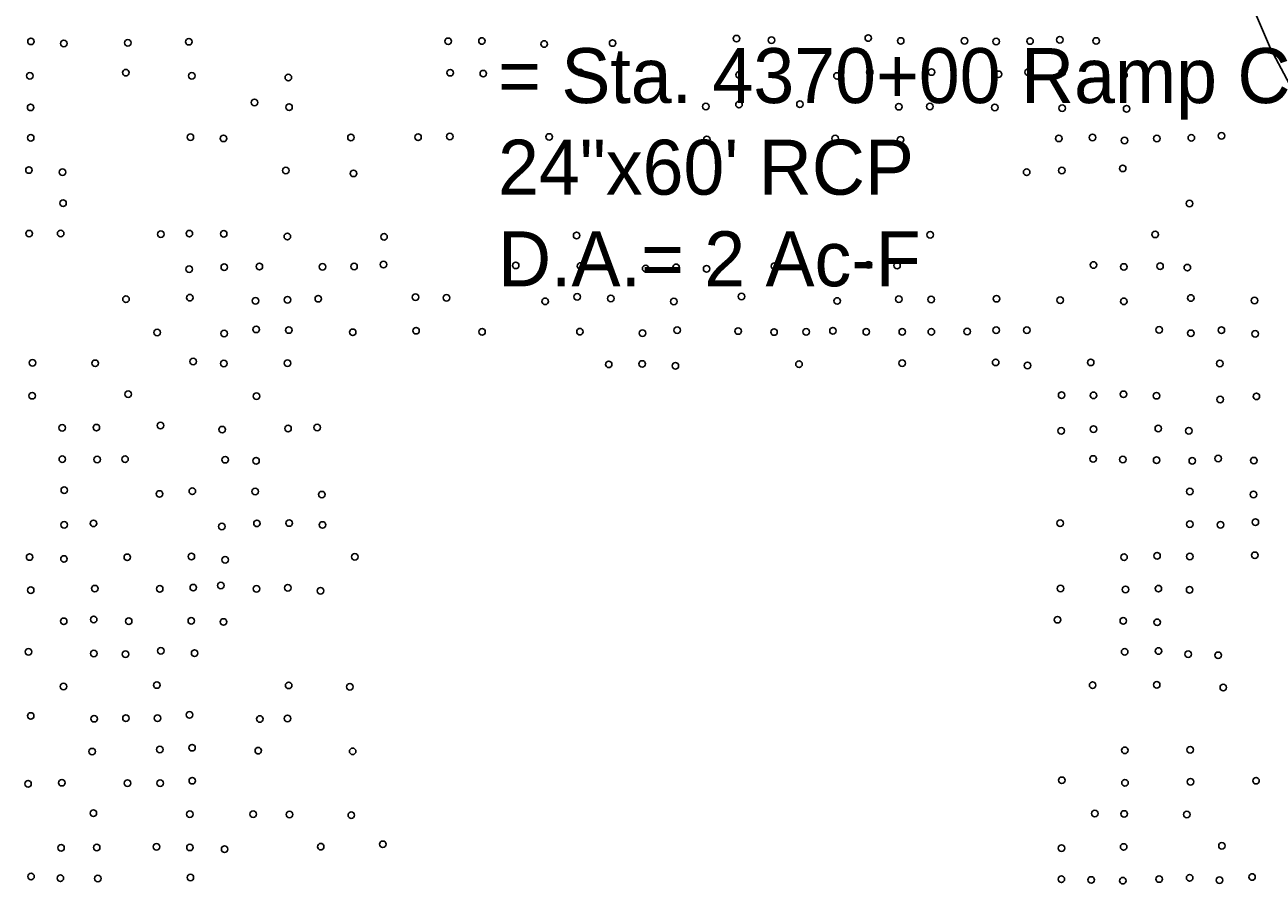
# Model space of a CAD drawing. Extents: x 20503438 to 20508873, y 7964251 to 7984667.
# Drawn here: x 20506056 to 20506434.7, y 7969482.5 to 7969745.2 of the extents above; entities that cross this region are included whole.
import ezdxf

# ---------------------------------------------------------------- set-up
doc = ezdxf.new("R2010")
doc.units = 0
for name, color, linetype in [('SurBreakLine', 7, 'Continuous'), ('SurSurveyPoints', 7, 'Continuous'), ('SurTxtDrainage', 7, 'Continuous')]:
    doc.layers.add(name, color=color, linetype=linetype)

msp = doc.modelspace()

# ---------------------------------------------------------------- linework, layer by layer
at = {"layer": 'SurBreakLine'}
msp.add_lwpolyline([(20506245.46, 7970059.26), (20506289.42, 7969989.86), (20506322.08, 7969939.84), (20506362.1, 7969878.45), (20506391.2, 7969829.89), (20506418.64, 7969776.17), (20506425.78, 7969763.92), (20506436.91, 7969737.91), (20506455.83, 7969702.3), (20506472.72, 7969660.29), (20506490.33, 7969606.63), (20506502.81, 7969561.31), (20506518.36, 7969500.09), (20506526.15, 7969455.03)], dxfattribs=at)
at = {"layer": 'SurSurveyPoints'}
for centre in [(20506057.92, 7969740.08), (20506067.96, 7969739.46), (20506087.52, 7969739.64), (20506106.22, 7969739.98), (20506185.5, 7969740.11), (20506195.81, 7969740.2), (20506214.85, 7969739.28), (20506235.76, 7969739.57), (20506273.66, 7969740.92), (20506284.32, 7969740.47), (20506313.93, 7969741.11), (20506323.84, 7969740.21), (20506343.38, 7969740.24), (20506353.02, 7969740.02), (20506363.38, 7969740.19), (20506372.48, 7969740.58), (20506383.6, 7969740.21), (20506225.82, 7969730.6), (20506314.37, 7969730.68), (20506333.23, 7969730.71), (20506362.81, 7969730.66), (20506373.21, 7969730.59), (20506057.59, 7969729.56), (20506086.93, 7969730.52), (20506107.1, 7969729.54), (20506136.61, 7969729.01), (20506186.12, 7969730.51), (20506196.22, 7969730.22), (20506274.42, 7969729.82), (20506304.37, 7969729.51), (20506353.75, 7969730.02), (20506392.12, 7969729.77), (20506057.82, 7969719.91), (20506126.25, 7969721.42), (20506136.83, 7969720), (20506264.28, 7969720.15), (20506274.4, 7969720.75), (20506293.04, 7969720.89), (20506323.27, 7969720.11), (20506332.76, 7969720.15), (20506352.61, 7969719.89), (20506373.19, 7969719.66), (20506392.92, 7969719.49), (20506057.85, 7969710.6), (20506106.67, 7969710.8), (20506116.78, 7969710.44), (20506155.76, 7969710.73), (20506176.27, 7969710.78), (20506185.97, 7969711.02), (20506216.39, 7969710.87), (20506264.55, 7969710.12), (20506303.79, 7969710.4), (20506323.79, 7969710.03), (20506372.18, 7969710.44), (20506382.5, 7969710.73), (20506392.29, 7969709.8), (20506402.18, 7969710.38), (20506412.7, 7969710.59), (20506421.93, 7969711.21), (20506057.31, 7969700.76), (20506135.84, 7969700.61), (20506373.11, 7969700.61), (20506391.72, 7969701.26), (20506067.54, 7969700.1), (20506156.52, 7969699.74), (20506362.36, 7969700.08), (20506067.73, 7969690.64), (20506412.15, 7969690.51), (20506067.01, 7969681.35), (20506057.36, 7969681.32), (20506097.65, 7969681.17), (20506106.35, 7969681.32), (20506116.85, 7969681.25), (20506136.31, 7969680.41), (20506165.87, 7969680.32), (20506224.76, 7969680.77), (20506332.88, 7969680.97), (20506401.65, 7969681.09), (20506106.31, 7969670.47), (20506117.04, 7969671.08), (20506127.76, 7969671.24), (20506147.05, 7969671.17), (20506156.71, 7969671.29), (20506165.69, 7969671.86), (20506206.13, 7969671.62), (20506225.97, 7969671.42), (20506234.6, 7969671.19), (20506245.87, 7969670.67), (20506255.15, 7969671.02), (20506264.51, 7969670.57), (20506285.25, 7969671.38), (20506314.03, 7969671.79), (20506322.72, 7969671.56), (20506382.76, 7969671.73), (20506392.07, 7969671.13), (20506403.13, 7969671.37), (20506411.48, 7969670.93), (20506086.98, 7969661.27), (20506106.48, 7969661.74), (20506126.59, 7969660.77), (20506136.34, 7969661.11), (20506145.78, 7969661.42), (20506175.51, 7969661.88), (20506184.95, 7969661.68), (20506215.14, 7969660.62), (20506224.91, 7969661.98), (20506235.19, 7969661.51), (20506254.49, 7969660.58), (20506275.15, 7969662.1), (20506304.42, 7969660.73), (20506323.3, 7969661.28), (20506333.13, 7969661.21), (20506353.11, 7969661.43), (20506372.63, 7969660.95), (20506392.07, 7969660.62), (20506412.54, 7969661.64), (20506432.04, 7969660.86), (20506096.52, 7969651.1), (20506126.79, 7969652.05), (20506136.76, 7969651.85), (20506156.3, 7969651.16), (20506175.66, 7969651.65), (20506195.84, 7969651.3), (20506225.78, 7969651.35), (20506255.48, 7969651.81), (20506274.12, 7969651.54), (20506285.12, 7969651.24), (20506294.91, 7969651.27), (20506303.13, 7969651.63), (20506313.32, 7969651.3), (20506324.33, 7969651.3), (20506333.21, 7969651.29), (20506344.16, 7969651.43), (20506353.03, 7969651.79), (20506362.38, 7969651.81), (20506402.85, 7969651.88), (20506421.89, 7969651.82), (20506116.97, 7969650.77), (20506244.93, 7969650.9), (20506412.57, 7969650.85), (20506432.22, 7969650.68), (20506058.41, 7969641.82), (20506077.56, 7969641.68), (20506107.52, 7969642.25), (20506116.92, 7969641.63), (20506136.38, 7969641.74), (20506234.57, 7969641.36), (20506244.8, 7969641.48), (20506254.95, 7969640.92), (20506292.75, 7969641.43), (20506324.3, 7969641.74), (20506352.88, 7969641.97), (20506362.63, 7969641.03), (20506381.94, 7969641.96), (20506421.41, 7969641.64), (20506087.64, 7969632.25), (20506391.94, 7969632.21), (20506058.32, 7969631.77), (20506126.86, 7969631.65), (20506373.04, 7969631.94), (20506382.8, 7969631.89), (20506402.04, 7969631.77), (20506421.53, 7969630.59), (20506432.59, 7969631.58), (20506067.49, 7969621.96), (20506077.92, 7969622.02), (20506097.51, 7969622.64), (20506116.39, 7969621.41), (20506136.53, 7969621.73), (20506145.44, 7969622.05), (20506372.92, 7969621.01), (20506382.82, 7969621.57), (20506402.6, 7969621.75), (20506411.91, 7969621.07), (20506067.51, 7969612.37), (20506078.14, 7969612.27), (20506086.68, 7969612.37), (20506117.33, 7969612.21), (20506126.74, 7969611.9), (20506382.67, 7969612.44), (20506391.79, 7969612.26), (20506402.09, 7969612.09), (20506412.99, 7969611.86), (20506420.9, 7969612.58), (20506431.83, 7969611.93), (20506068.11, 7969602.9), (20506107.26, 7969602.57), (20506126.45, 7969602.49), (20506412.25, 7969602.5), (20506097.22, 7969601.74), (20506146.86, 7969601.54), (20506431.7, 7969601.6), (20506068.05, 7969592.29), (20506077.07, 7969592.76), (20506116.29, 7969591.82), (20506127.02, 7969592.76), (20506136.88, 7969592.85), (20506147.04, 7969592.27), (20506372.59, 7969592.79), (20506412.24, 7969592.5), (20506421.65, 7969592.33), (20506432.28, 7969593.12), (20506432.12, 7969583), (20506057.51, 7969582.46), (20506068.02, 7969581.87), (20506087.38, 7969582.39), (20506106.97, 7969582.62), (20506117.27, 7969581.63), (20506156.92, 7969582.54), (20506392.12, 7969582.43), (20506402.22, 7969582.86), (20506412.23, 7969582.62), (20506057.85, 7969572.32), (20506077.44, 7969572.81), (20506097.29, 7969572.72), (20506107.56, 7969573.11), (20506116, 7969573.76), (20506126.87, 7969572.73), (20506136.45, 7969573.07), (20506146.42, 7969572.16), (20506372.72, 7969572.86), (20506392.6, 7969572.57), (20506402.63, 7969572.8), (20506412.18, 7969572.43), (20506067.94, 7969562.82), (20506077.1, 7969563.4), (20506087.81, 7969562.87), (20506106.95, 7969562.97), (20506116.78, 7969562.62), (20506371.79, 7969563.31), (20506391.9, 7969562.94), (20506402.27, 7969562.51), (20506057.14, 7969553.48), (20506077.14, 7969552.98), (20506086.85, 7969552.77), (20506097.64, 7969553.8), (20506107.96, 7969553.11), (20506392.32, 7969553.48), (20506402.65, 7969553.74), (20506411.71, 7969552.78), (20506420.9, 7969552.43), (20506067.87, 7969542.9), (20506096.43, 7969543.34), (20506136.72, 7969543.24), (20506155.43, 7969542.82), (20506382.53, 7969543.32), (20506402.12, 7969543.41), (20506422.47, 7969542.56), (20506057.85, 7969533.88), (20506106.4, 7969534.21), (20506077.24, 7969533.04), (20506086.97, 7969533.23), (20506096.61, 7969533.18), (20506127.92, 7969532.96), (20506136.38, 7969533.13), (20506076.62, 7969522.99), (20506097.3, 7969523.64), (20506107.17, 7969524.18), (20506127.43, 7969523.28), (20506156.28, 7969523.07), (20506392.39, 7969523.38), (20506412.37, 7969523.56), (20506057.03, 7969513.17), (20506067.39, 7969513.48), (20506087.47, 7969513.37), (20506097.42, 7969513.37), (20506107.25, 7969514.09), (20506373.08, 7969514.22), (20506392.42, 7969513.45), (20506412.44, 7969513.78), (20506432.48, 7969514.1), (20506077, 7969504.16), (20506106.51, 7969503.86), (20506125.86, 7969503.86), (20506136.97, 7969503.76), (20506155.87, 7969503.57), (20506383.17, 7969504.04), (20506392.15, 7969503.93), (20506411.33, 7969503.75), (20506067.12, 7969493.57), (20506078.02, 7969493.67), (20506096.3, 7969493.89), (20506106.53, 7969493.72), (20506117.13, 7969493.16), (20506146.51, 7969493.93), (20506165.5, 7969494.66), (20506373.01, 7969493.5), (20506392.01, 7969493.85), (20506422.06, 7969494.2), (20506057.94, 7969484.79), (20506106.67, 7969484.49), (20506431.26, 7969484.66), (20506066.91, 7969484.28), (20506078.39, 7969484.18), (20506372.96, 7969483.97), (20506382.1, 7969483.76), (20506391.78, 7969483.54), (20506402.86, 7969484.04), (20506412.19, 7969484.38), (20506421.29, 7969483.71)]:
    msp.add_circle(centre, 1, dxfattribs=at)

# ---------------------------------------------------------------- texts
at = {"layer": 'SurTxtDrainage'}
for s, p in [('= Sta. 4370+00 Ramp C', (20506200.73, 7969721.22)), ('24"x60\' RCP', (20506200.73, 7969693.22)), ('D.A.= 2 Ac-F', (20506200.73, 7969665.22))]:
    msp.add_text(s, height=16.8, dxfattribs=at).set_placement(p)

doc.saveas('drawing.dxf')
